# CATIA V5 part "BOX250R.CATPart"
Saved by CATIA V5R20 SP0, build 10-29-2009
Part number: BOX250R
Bounding box of the stored display mesh (mm): x 0 to 391, y -20 to 55, z -41.5 to 15
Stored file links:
  C:\Users\Utente\Desktop\IO LAVORO\3D X SITO CF\X SITO\PLASTICA\BOX\BOX250R.CATPart
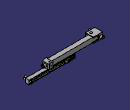
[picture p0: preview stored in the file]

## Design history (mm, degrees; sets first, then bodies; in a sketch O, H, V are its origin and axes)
Set1
  DatumSurface1 to DatumSurface16 "_ZH90/3_head"
  DatumSurface17 to DatumSurface34 "_ZH90/3_screw1"
  DatumSurface35 to DatumSurface55 "_ZH90/3_hand"
  DatumSurface56 to DatumSurface73 "_ZH90/3_screw2"
  DatumSurface74 to DatumSurface94 "_ZH90/3_he"
  DatumSurface95 to DatumSurface109 "_ZH90/3_screw3"
  DatumSurface110 to DatumSurface117 "_ZH90/3_stift1"
  DatumSurface118 to DatumSurface127 "_ZH90/3_stift2"
  DatumSurface128 to DatumSurface1029 "_ZH90/06_body"
  DatumSurface1030 to DatumSurface1047 "_M8-5"
  DatumSurface1048 to DatumSurface1067 "_ST2"
  DatumSurface1068 to DatumSurface1113 "_ZH90/06_foot1u"
  DatumSurface1114 to DatumSurface1136 "_ZH90/06_foot1d"
  DatumSurface1137 to DatumSurface1154 "_M5-1"
  DatumSurface1155 to DatumSurface1177 "_ZH90/06_foot2u"
  DatumSurface1178 to DatumSurface1211 "_ZH90/06_foot2d"
  DatumSurface1212 to DatumSurface1229 "_M5-2"
Body1 (main body)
